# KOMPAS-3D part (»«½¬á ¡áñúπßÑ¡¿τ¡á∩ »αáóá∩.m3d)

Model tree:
1. Эскиз:1
2. Операция выдавливания:1
     Расстояние 1 = 2
3. Эскиз:2
4. Операция выдавливания:2
     Расстояние 1 = 3
5. Эскиз:3
6. Вырезать элемент выдавливания:1
     Расстояние 1 = 38.8
7. Эскиз:4
8. Операция выдавливания:3
     Расстояние 1 = 10
9. Эскиз:6
10. Операция выдавливания:4
     Расстояние 1 = 10
11. Эскиз:9
12. Вырезать элемент выдавливания:4
     Расстояние 1 = 1
13. Эскиз:11
14. Вырезать элемент выдавливания:5
     Расстояние 1 = 2
15. Эскиз:15
16. Вырезать элемент выдавливания:8
     Расстояние 1 = 310
17. Эскиз:16
18. Операция выдавливания:5
     Расстояние 1 = 0.3; Расстояние 2 = 36.8
19. Скругление:1
     Радиус = 2

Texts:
  полка надгусеничная правая
  Сплав АЛ8  ГОСТ 1583-93
  stalker61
